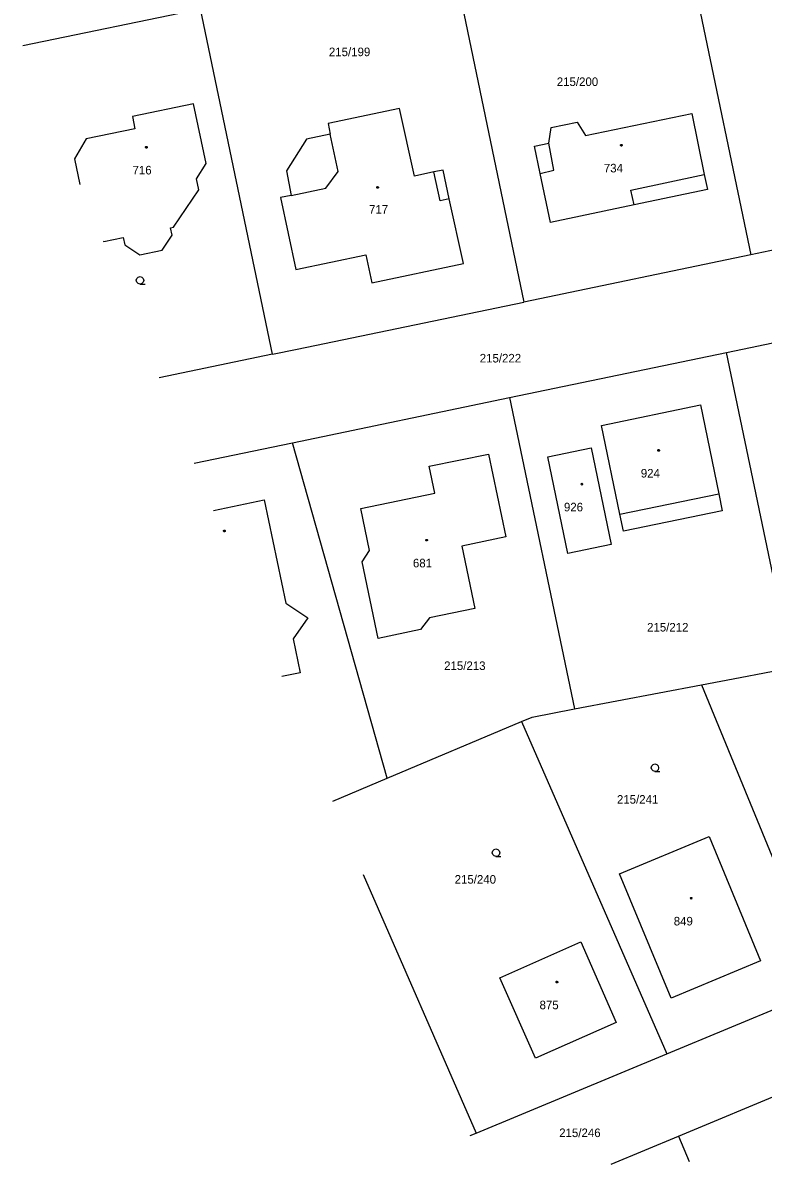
# Model space of a CAD drawing. Extents: x -757994 to -755874, y -1047691 to -1046119.
# Drawn here: x -757732.9 to -757659.5, y -1047691.1 to -1047577.8 of the extents above; entities that cross this region are included whole.
import ezdxf

# ---------------------------------------------------------------- set-up
doc = ezdxf.new("R2010")
doc.units = 0
doc.layers.add('katastrální mapa', color=7, linetype='Continuous')

msp = doc.modelspace()

# ---------------------------------------------------------------- linework, layer by layer
at = {"layer": 'katastrální mapa'}
for p, q in [((-757667.79, -1047566.64), (-757660.68, -1047600.86)), ((-757690.32, -1047571.28), (-757683.2, -1047605.55)), ((-757732.94, -1047580.08), (-757715.29, -1047576.44)), ((-757708.16, -1047610.74), (-757715.29, -1047576.44)), ((-757715.99, -1047585.88), (-757722.06, -1047587.14)), ((-757714.75, -1047591.78), (-757715.99, -1047585.88)), ((-757722.06, -1047587.14), (-757721.81, -1047588.36)), ((-757680.51, -1047588.21), (-757677.93, -1047587.68)), ((-757677.93, -1047587.68), (-757677.1, -1047589.03)), ((-757677.1, -1047589.03), (-757666.55, -1047586.83)), ((-757666.55, -1047586.83), (-757665.3, -1047592.9)), ((-757721.81, -1047588.36), (-757726.64, -1047589.36)), ((-757680.72, -1047589.79), (-757680.51, -1047588.21)), ((-757726.64, -1047589.36), (-757727.81, -1047591.33)), ((-757682.14, -1047590.08), (-757680.72, -1047589.79)), ((-757680.24, -1047592.47), (-757680.72, -1047589.79)), ((-757681.58, -1047592.8), (-757682.14, -1047590.08)), ((-757727.81, -1047591.33), (-757727.28, -1047593.88)), ((-757715.71, -1047593.31), (-757714.75, -1047591.78)), ((-757715.48, -1047594.41), (-757715.71, -1047593.31)), ((-757681.58, -1047592.8), (-757680.24, -1047592.47)), ((-757680.57, -1047597.65), (-757681.58, -1047592.8)), ((-757672.59, -1047594.44), (-757665.3, -1047592.9)), ((-757665.3, -1047592.9), (-757664.99, -1047594.38)), ((-757717.99, -1047598.12), (-757715.48, -1047594.41)), ((-757672.25, -1047595.9), (-757672.59, -1047594.44)), ((-757664.99, -1047594.38), (-757672.25, -1047595.9)), ((-757672.25, -1047595.9), (-757680.57, -1047597.65)), ((-757638.16, -1047596.18), (-757660.68, -1047600.86)), ((-757719.12, -1047600.41), (-757718.13, -1047598.9)), ((-757718.29, -1047598.18), (-757717.99, -1047598.12)), ((-757718.13, -1047598.9), (-757718.29, -1047598.18)), ((-757724.97, -1047599.49), (-757724.89, -1047599.55)), ((-757724.89, -1047599.55), (-757722.98, -1047599.15)), ((-757722.98, -1047599.15), (-757722.83, -1047599.88)), ((-757722.83, -1047599.88), (-757721.32, -1047600.87)), ((-757721.32, -1047600.87), (-757719.12, -1047600.41)), ((-757660.68, -1047600.86), (-757683.2, -1047605.55)), ((-757705.71, -1047610.24), (-757683.2, -1047605.55)), ((-757663.08, -1047610.56), (-757643.99, -1047606.59)), ((-757708.16, -1047610.74), (-757705.71, -1047610.24)), ((-757708.16, -1047610.74), (-757719.4, -1047613.08)), ((-757684.62, -1047615.04), (-757663.08, -1047610.56)), ((-757656.58, -1047641.82), (-757663.08, -1047610.56)), ((-757706.16, -1047619.52), (-757684.62, -1047615.04)), ((-757684.62, -1047615.04), (-757678.18, -1047645.95)), ((-757675.49, -1047617.81), (-757665.68, -1047615.77)), ((-757665.68, -1047615.77), (-757663.87, -1047624.58)), ((-757673.67, -1047626.61), (-757675.49, -1047617.81)), ((-757715.92, -1047621.55), (-757706.16, -1047619.52)), ((-757696.79, -1047652.82), (-757706.16, -1047619.52)), ((-757692.6, -1047621.83), (-757686.72, -1047620.64)), ((-757686.72, -1047620.64), (-757685.01, -1047628.86)), ((-757680.82, -1047620.91), (-757676.52, -1047620.03)), ((-757676.52, -1047620.03), (-757674.54, -1047629.63)), ((-757678.84, -1047630.5), (-757680.82, -1047620.91)), ((-757692.05, -1047624.51), (-757692.6, -1047621.83)), ((-757714, -1047626.25), (-757708.99, -1047625.18)), ((-757708.99, -1047625.18), (-757706.84, -1047635.45)), ((-757699.39, -1047626.04), (-757692.05, -1047624.51)), ((-757673.67, -1047626.61), (-757663.87, -1047624.58)), ((-757663.87, -1047624.58), (-757663.52, -1047626.27)), ((-757698.52, -1047630.2), (-757699.39, -1047626.04)), ((-757663.52, -1047626.27), (-757673.33, -1047628.31)), ((-757673.33, -1047628.31), (-757673.67, -1047626.61)), ((-757685.01, -1047628.86), (-757689.38, -1047629.77)), ((-757674.54, -1047629.63), (-757678.84, -1047630.5)), ((-757699.26, -1047631.33), (-757698.52, -1047630.2)), ((-757689.38, -1047629.77), (-757688.09, -1047635.96)), ((-757697.67, -1047638.94), (-757699.26, -1047631.33)), ((-757706.84, -1047635.45), (-757704.65, -1047636.89)), ((-757688.09, -1047635.96), (-757692.57, -1047636.89)), ((-757704.65, -1047636.89), (-757706.11, -1047638.98)), ((-757692.57, -1047636.89), (-757693.46, -1047638.07)), ((-757693.46, -1047638.07), (-757697.67, -1047638.94)), ((-757706.11, -1047638.98), (-757705.41, -1047642.35)), ((-757661.74, -1047642.81), (-757656.58, -1047641.82)), ((-757705.41, -1047642.35), (-757707.23, -1047642.74)), ((-757665.59, -1047643.54), (-757661.74, -1047642.81)), ((-757678.18, -1047645.95), (-757665.59, -1047643.54)), ((-757665.59, -1047643.54), (-757653.23, -1047673.62)), ((-757682.37, -1047646.75), (-757678.18, -1047645.95)), ((-757696.79, -1047652.82), (-757683.44, -1047647.2)), ((-757683.44, -1047647.2), (-757682.37, -1047646.75)), ((-757683.44, -1047647.2), (-757669.02, -1047680.18)), ((-757702.16, -1047655.09), (-757696.79, -1047652.82)), ((-757673.72, -1047662.33), (-757664.83, -1047658.62)), ((-757664.83, -1047658.62), (-757659.72, -1047670.94)), ((-757699.17, -1047662.39), (-757687.94, -1047688.05)), ((-757668.6, -1047674.65), (-757673.72, -1047662.33)), ((-757685.61, -1047672.64), (-757677.57, -1047669.08)), ((-757677.57, -1047669.08), (-757674.04, -1047677.08)), ((-757659.72, -1047670.94), (-757668.6, -1047674.65)), ((-757682.06, -1047680.62), (-757685.61, -1047672.64)), ((-757669.02, -1047680.18), (-757653.23, -1047673.62)), ((-757674.04, -1047677.08), (-757682.06, -1047680.62)), ((-757667.85, -1047688.35), (-757645.64, -1047679.12)), ((-757687.94, -1047688.05), (-757669.02, -1047680.18)), ((-757688.54, -1047688.3), (-757687.94, -1047688.05)), ((-757674.55, -1047691.14), (-757667.85, -1047688.35)), ((-757667.85, -1047688.35), (-757666.79, -1047690.89))]:
    msp.add_line(p, q, dxfattribs=at)
for points in [[(-757692.15, -1047592.63), (-757694.07, -1047593.06), (-757695.54, -1047586.35), (-757702.62, -1047587.82), (-757702.44, -1047588.89)], [(-757702.44, -1047588.89), (-757704.79, -1047589.38), (-757706.78, -1047592.54), (-757706.3, -1047594.96)], [(-757706.3, -1047594.96), (-757702.88, -1047594.25), (-757701.65, -1047592.59), (-757702.44, -1047588.89)], [(-757690.61, -1047595.29), (-757691.23, -1047592.46), (-757692.15, -1047592.63)], [(-757690.61, -1047595.29), (-757691.53, -1047595.5), (-757692.15, -1047592.63)], [(-757706.3, -1047594.96), (-757707.35, -1047595.18), (-757705.85, -1047602.31)], [(-757705.85, -1047602.31), (-757698.91, -1047600.87), (-757698.3, -1047603.63), (-757689.19, -1047601.74), (-757690.61, -1047595.29)], [(-757721.3, -1047603.76), (-757721.49, -1047603.71), (-757721.62, -1047603.58), (-757721.68, -1047603.39), (-757721.62, -1047603.21), (-757721.49, -1047603.07), (-757721.31, -1047603.02), (-757721.12, -1047603.07), (-757720.99, -1047603.21), (-757720.94, -1047603.4), (-757720.99, -1047603.59), (-757721.12, -1047603.72), (-757721.31, -1047603.77), (-757720.81, -1047603.77)], [(-757670.19, -1047652.15), (-757670.38, -1047652.1), (-757670.51, -1047651.97), (-757670.57, -1047651.78), (-757670.51, -1047651.6), (-757670.38, -1047651.46), (-757670.2, -1047651.41), (-757670.01, -1047651.46), (-757669.88, -1047651.6), (-757669.83, -1047651.79), (-757669.88, -1047651.98), (-757670.01, -1047652.11), (-757670.2, -1047652.16), (-757669.7, -1047652.16)], [(-757685.97, -1047660.59), (-757686.16, -1047660.54), (-757686.29, -1047660.41), (-757686.35, -1047660.22), (-757686.29, -1047660.03), (-757686.16, -1047659.9), (-757685.98, -1047659.85), (-757685.79, -1047659.9), (-757685.66, -1047660.03), (-757685.6, -1047660.23), (-757685.66, -1047660.42), (-757685.79, -1047660.55), (-757685.98, -1047660.6), (-757685.48, -1047660.6)]]:
    msp.add_lwpolyline(points, dxfattribs=at)
for points in [[(-757673.52, -1047589.9), (-757673.47, -1047589.91), (-757673.45, -1047589.95), (-757673.44, -1047589.98), (-757673.45, -1047590.02), (-757673.49, -1047590.06), (-757673.52, -1047590.07), (-757673.57, -1047590.05), (-757673.6, -1047590.02), (-757673.6, -1047589.98), (-757673.6, -1047589.94), (-757673.55, -1047589.9)], [(-757720.69, -1047590.1), (-757720.64, -1047590.11), (-757720.61, -1047590.15), (-757720.6, -1047590.18), (-757720.61, -1047590.23), (-757720.66, -1047590.26), (-757720.69, -1047590.27), (-757720.73, -1047590.25), (-757720.76, -1047590.22), (-757720.77, -1047590.18), (-757720.76, -1047590.14), (-757720.72, -1047590.1)], [(-757697.72, -1047594.09), (-757697.67, -1047594.1), (-757697.65, -1047594.14), (-757697.64, -1047594.17), (-757697.65, -1047594.22), (-757697.69, -1047594.25), (-757697.72, -1047594.26), (-757697.76, -1047594.24), (-757697.79, -1047594.21), (-757697.8, -1047594.17), (-757697.79, -1047594.12), (-757697.75, -1047594.09)], [(-757669.83, -1047620.19), (-757669.78, -1047620.2), (-757669.75, -1047620.24), (-757669.74, -1047620.27), (-757669.75, -1047620.32), (-757669.79, -1047620.35), (-757669.83, -1047620.36), (-757669.88, -1047620.34), (-757669.91, -1047620.31), (-757669.92, -1047620.27), (-757669.91, -1047620.23), (-757669.86, -1047620.19)], [(-757677.46, -1047623.54), (-757677.41, -1047623.55), (-757677.39, -1047623.6), (-757677.38, -1047623.63), (-757677.39, -1047623.68), (-757677.43, -1047623.71), (-757677.46, -1047623.72), (-757677.5, -1047623.7), (-757677.53, -1047623.67), (-757677.54, -1047623.63), (-757677.53, -1047623.59), (-757677.49, -1047623.55)], [(-757712.94, -1047628.19), (-757712.89, -1047628.2), (-757712.86, -1047628.24), (-757712.85, -1047628.27), (-757712.86, -1047628.32), (-757712.91, -1047628.35), (-757712.94, -1047628.36), (-757712.98, -1047628.34), (-757713.01, -1047628.31), (-757713.02, -1047628.27), (-757713.01, -1047628.23), (-757712.97, -1047628.19)], [(-757692.86, -1047629.11), (-757692.81, -1047629.12), (-757692.78, -1047629.16), (-757692.77, -1047629.19), (-757692.78, -1047629.23), (-757692.83, -1047629.27), (-757692.86, -1047629.27), (-757692.91, -1047629.26), (-757692.94, -1047629.23), (-757692.95, -1047629.19), (-757692.94, -1047629.15), (-757692.9, -1047629.11)], [(-757666.6, -1047664.66), (-757666.55, -1047664.67), (-757666.52, -1047664.71), (-757666.51, -1047664.74), (-757666.52, -1047664.78), (-757666.57, -1047664.82), (-757666.6, -1047664.83), (-757666.65, -1047664.81), (-757666.68, -1047664.78), (-757666.69, -1047664.74), (-757666.68, -1047664.7), (-757666.64, -1047664.66)], [(-757679.92, -1047672.98), (-757679.87, -1047672.99), (-757679.85, -1047673.03), (-757679.84, -1047673.06), (-757679.85, -1047673.11), (-757679.89, -1047673.14), (-757679.92, -1047673.15), (-757679.97, -1047673.13), (-757680, -1047673.1), (-757680.01, -1047673.06), (-757680, -1047673.02), (-757679.96, -1047672.98)]]:
    msp.add_lwpolyline(points, close=True, dxfattribs=at)

# ---------------------------------------------------------------- texts
for s, p in [('215/199', (-757702.56, -1047581.14)), ('215/200', (-757679.94, -1047584.1)), ('716', (-757722.05, -1047592.88)), ('734', (-757675.27, -1047592.68)), ('717', (-757698.58, -1047596.78)), ('215/222', (-757687.59, -1047611.55)), ('924', (-757671.6, -1047622.97)), ('926', (-757679.23, -1047626.33)), ('681', (-757694.22, -1047631.89)), ('215/212', (-757670.98, -1047638.26)), ('215/213', (-757691.12, -1047642.08)), ('215/241', (-757673.97, -1047655.35)), ('215/240', (-757690.08, -1047663.29)), ('849', (-757668.33, -1047667.44)), ('875', (-757681.65, -1047675.76)), ('215/246', (-757679.7, -1047688.45))]:
    msp.add_text(s, height=0.85, dxfattribs=at).set_placement(p)

doc.saveas('drawing.dxf')
